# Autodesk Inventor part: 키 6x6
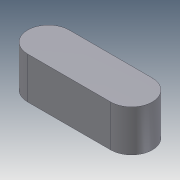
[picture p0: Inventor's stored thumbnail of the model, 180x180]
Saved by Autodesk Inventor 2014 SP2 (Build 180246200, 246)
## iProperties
Company: 한국ATC센터
Created: 2013-01
Part Number: 키 6x6
Document SubType Name: Modeling
Designer: KYOUNG IL JANG
Density: 7.25 g/cm^3
Material: 주철
Mass: 4.36193 g
Surface Area: 4.57646 cm^2
Volume: 0.601646 cm^3
Appearance: 강철
Author: KYOUNG IL JANG
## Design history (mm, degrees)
sketch "스케치1"
  geometry: L1 (-6, -3)-(6, -3); L2 (6, 3)-(-6, 3); A1 r 3 centre (6, 0) between (6, -3) and (6, 3); A2 r 3 centre (-6, 0) between (-6, 3) and (-6, -3); 2 further points
  constraints: 4 end point, 4 point on circle, 4 tangent, 2 centre point, 1 horizontal, 1 horizontal alignment, 1 midpoint, 1 parallel, 1 vertical alignment
  dimensions: "d0" = 18 dimension on A1 A2; "d1" = 6 distance between parallel lines of L1 L2
extrude "돌출1" new body sketch "스케치1" stored distance "d2" = 6; taper "d3" = 0 deg
node "솔리드1"
